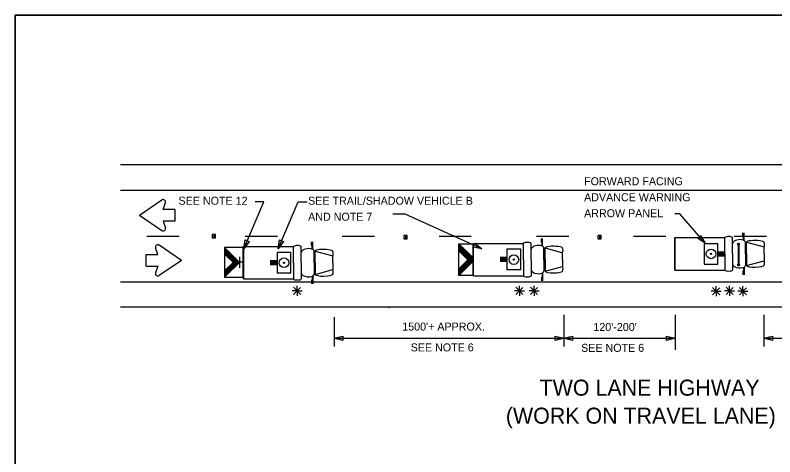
# Model space of a CAD drawing. Extents: x 1374027 to 1374537, y 380415 to 381405.
# Drawn here: x 1374027.1 to 1374084, y 381372.1 to 381405.2 of the extents above; entities that cross this region are included whole.
import ezdxf

# ---------------------------------------------------------------- set-up
doc = ezdxf.new("R2010")
doc.units = 0
for name, color, linetype in [('DSN_DRFT_Junk-No-Plot', 7, 'Continuous'), ('Level 1', 7, 'Continuous'), ('Working Level 1', 7, 'Continuous')]:
    doc.layers.add(name, color=color, linetype=linetype)

msp = doc.modelspace()

# ---------------------------------------------------------------- linework, layer by layer
at = {"layer": 'DSN_DRFT_Junk-No-Plot'}
for points in [[(1374027.083, 381405.174), (1374197.083, 381405.174), (1374197.083, 381295.174), (1374027.083, 381295.174)], [(1374027.083, 381405.174), (1374027.083, 381295.174), (1374197.083, 381295.174), (1374197.083, 381405.174)]]:
    msp.add_lwpolyline(points, close=True, dxfattribs=at)
at = {"layer": 'Level 1'}
for points in [[(1374044.225, 381387.656), (1374045.73, 381391.182), (1374045.061, 381391.182)], [(1374046.798, 381387.656), (1374048.302, 381391.182), (1374048.971, 381391.182)], [(1374062.052, 381387.656), (1374056.327, 381390.262), (1374055.393, 381390.262)]]:
    msp.add_lwpolyline(points, dxfattribs=at)
at = {"layer": 'Working Level 1'}
for p, q in [((1374034.976, 381393.968), (1374114.952, 381393.968)), ((1374034.976, 381392.056), (1374114.952, 381392.056)), ((1374036.403, 381390.173), (1374038.07, 381391.316)), ((1374038.175, 381390.609), (1374038.338, 381391.117)), ((1374039.043, 381390.609), (1374038.175, 381390.609)), ((1374039.043, 381390.609), (1374039.043, 381389.736)), ((1374036.403, 381390.173), (1374038.07, 381389.029)), ((1374039.043, 381389.736), (1374038.175, 381389.736)), ((1374038.175, 381389.736), (1374038.338, 381389.229)), ((1374041.846, 381388.717), (1374041.845, 381388.474)), ((1374042.088, 381388.717), (1374041.846, 381388.717)), ((1374041.968, 381388.717), (1374041.967, 381388.474)), ((1374042.088, 381388.474), (1374042.088, 381388.717)), ((1374056.214, 381388.642), (1374056.213, 381388.399)), ((1374056.456, 381388.642), (1374056.214, 381388.642)), ((1374056.335, 381388.642), (1374056.335, 381388.399)), ((1374056.456, 381388.399), (1374056.456, 381388.642)), ((1374070.758, 381388.656), (1374070.757, 381388.413)), ((1374071, 381388.656), (1374070.758, 381388.656)), ((1374070.879, 381388.656), (1374070.879, 381388.413)), ((1374071, 381388.413), (1374071, 381388.656)), ((1374081.635, 381388.562), (1374081.635, 381388.858)), ((1374081.682, 381388.276), (1374081.682, 381388.858)), ((1374081.722, 381388.276), (1374081.722, 381388.858)), ((1374041.845, 381388.474), (1374042.088, 381388.474)), ((1374049.302, 381387.891), (1374049.302, 381388.188)), ((1374049.349, 381387.605), (1374049.349, 381388.188)), ((1374049.389, 381387.605), (1374049.389, 381388.188)), ((1374056.213, 381388.399), (1374056.456, 381388.399)), ((1374061.427, 381388.059), (1374065.181, 381388.059)), ((1374061.427, 381385.634), (1374061.427, 381388.059)), ((1374065.181, 381386.847), (1374065.181, 381388.059)), ((1374065.757, 381386.847), (1374065.757, 381388.059)), ((1374066.532, 381388.132), (1374066.532, 381388.429)), ((1374066.579, 381387.846), (1374066.579, 381388.429)), ((1374066.619, 381387.846), (1374066.619, 381388.429)), ((1374070.757, 381388.413), (1374071, 381388.413)), ((1374076.53, 381388.489), (1374080.284, 381388.489)), ((1374076.53, 381386.063), (1374076.53, 381388.489)), ((1374076.53, 381388.489), (1374076.53, 381386.064)), ((1374078.735, 381388.053), (1374079.761, 381388.053)), ((1374078.735, 381388.053), (1374078.735, 381386.5)), ((1374079.761, 381386.5), (1374079.761, 381388.053)), ((1374080.284, 381387.276), (1374080.284, 381388.489)), ((1374080.86, 381387.276), (1374080.86, 381388.489)), ((1374081.314, 381388.064), (1374081.314, 381388.064)), ((1374081.823, 381387.276), (1374081.823, 381388.15)), ((1374081.903, 381388.15), (1374083.216, 381387.791)), ((1374081.903, 381387.276), (1374081.903, 381388.15)), ((1374037.771, 381387.224), (1374037.608, 381387.731)), ((1374039.543, 381386.787), (1374037.876, 381387.931)), ((1374042.77, 381387.754), (1374043.889, 381386.637)), ((1374044.197, 381387.819), (1374044.197, 381385.393)), ((1374044.197, 381387.818), (1374047.951, 381387.818)), ((1374044.197, 381385.393), (1374044.197, 381387.818)), ((1374047.951, 381386.606), (1374047.951, 381387.818)), ((1374048.526, 381386.606), (1374048.526, 381387.818)), ((1374049.49, 381386.606), (1374049.49, 381387.479)), ((1374049.57, 381387.479), (1374050.883, 381387.12)), ((1374049.57, 381386.606), (1374049.57, 381387.479)), ((1374060.34, 381388.031), (1374061.376, 381386.996)), ((1374060.34, 381387.513), (1374061.023, 381386.833)), ((1374064.975, 381387.623), (1374063.948, 381387.623)), ((1374063.948, 381387.623), (1374063.948, 381386.07)), ((1374064.975, 381386.07), (1374064.975, 381387.623)), ((1374066.72, 381386.847), (1374066.72, 381387.72)), ((1374066.8, 381387.72), (1374068.113, 381387.361)), ((1374066.8, 381386.847), (1374066.8, 381387.72)), ((1374081.226, 381388.014), (1374081.226, 381388.014)), ((1374081.288, 381387.979), (1374081.288, 381386.473)), ((1374081.292, 381387.979), (1374081.292, 381386.473)), ((1374081.297, 381387.979), (1374081.297, 381386.473)), ((1374081.305, 381387.979), (1374081.305, 381386.473)), ((1374081.316, 381387.979), (1374081.316, 381386.473)), ((1374083.216, 381387.276), (1374083.216, 381387.791)), ((1374036.904, 381386.351), (1374036.904, 381387.224)), ((1374036.904, 381387.224), (1374037.771, 381387.224)), ((1374042.77, 381387.269), (1374043.411, 381386.63)), ((1374043.926, 381386.217), (1374043.926, 381387.058)), ((1374047.744, 381387.382), (1374046.718, 381387.382)), ((1374046.718, 381387.382), (1374046.718, 381385.829)), ((1374047.744, 381385.829), (1374047.744, 381387.382)), ((1374050.883, 381386.606), (1374050.883, 381387.12)), ((1374063.948, 381387.002), (1374063.426, 381387.002)), ((1374063.948, 381386.924), (1374063.426, 381386.924)), ((1374068.113, 381386.847), (1374068.113, 381387.361)), ((1374079.761, 381387.432), (1374080.284, 381387.432)), ((1374079.761, 381387.354), (1374080.284, 381387.354)), ((1374079.761, 381387.276), (1374080.284, 381387.276)), ((1374079.761, 381387.199), (1374080.284, 381387.199)), ((1374079.761, 381387.121), (1374080.284, 381387.121)), ((1374080.284, 381387.276), (1374080.284, 381386.064)), ((1374080.86, 381387.276), (1374080.86, 381386.064)), ((1374081.823, 381387.276), (1374081.823, 381386.403)), ((1374081.903, 381387.276), (1374081.903, 381386.403)), ((1374083.216, 381387.276), (1374083.216, 381386.762)), ((1374036.904, 381386.351), (1374037.771, 381386.351)), ((1374037.771, 381386.351), (1374037.608, 381385.844)), ((1374039.543, 381386.787), (1374037.876, 381385.644)), ((1374042.77, 381385.991), (1374043.411, 381386.63)), ((1374042.777, 381385.524), (1374043.889, 381386.637)), ((1374044.16, 381386.657), (1374043.919, 381386.657)), ((1374046.718, 381386.761), (1374046.195, 381386.761)), ((1374046.718, 381386.683), (1374046.195, 381386.683)), ((1374046.718, 381386.606), (1374046.195, 381386.606)), ((1374046.718, 381386.528), (1374046.195, 381386.528)), ((1374046.718, 381386.45), (1374046.195, 381386.45)), ((1374047.951, 381386.606), (1374047.951, 381385.393)), ((1374048.526, 381386.606), (1374048.526, 381385.393)), ((1374049.49, 381386.606), (1374049.49, 381385.732)), ((1374049.57, 381386.606), (1374049.57, 381385.732)), ((1374050.883, 381386.606), (1374050.883, 381386.091)), ((1374060.34, 381386.151), (1374061.023, 381386.833)), ((1374060.346, 381385.653), (1374061.371, 381386.678)), ((1374063.948, 381386.847), (1374063.426, 381386.847)), ((1374063.948, 381386.769), (1374063.426, 381386.769)), ((1374063.948, 381386.691), (1374063.426, 381386.691)), ((1374065.181, 381386.847), (1374065.181, 381385.634)), ((1374065.757, 381386.847), (1374065.757, 381385.634)), ((1374066.72, 381386.847), (1374066.72, 381385.973)), ((1374066.8, 381386.847), (1374066.8, 381385.973)), ((1374068.113, 381386.847), (1374068.113, 381386.332)), ((1374078.735, 381386.5), (1374079.761, 381386.5)), ((1374081.231, 381386.46), (1374081.231, 381386.46)), ((1374081.318, 381386.511), (1374081.318, 381386.511)), ((1374081.903, 381386.403), (1374083.216, 381386.762)), ((1374047.744, 381385.829), (1374046.718, 381385.829)), ((1374049.57, 381385.732), (1374050.883, 381386.091)), ((1374064.975, 381386.07), (1374063.948, 381386.07)), ((1374066.579, 381385.847), (1374066.579, 381385.264)), ((1374066.619, 381385.847), (1374066.619, 381385.264)), ((1374066.8, 381385.973), (1374068.113, 381386.332)), ((1374076.53, 381386.064), (1374080.284, 381386.064)), ((1374081.635, 381385.991), (1374081.635, 381385.694)), ((1374081.682, 381386.277), (1374081.682, 381385.694)), ((1374081.722, 381386.277), (1374081.722, 381385.694)), ((1374044.197, 381385.393), (1374047.951, 381385.393)), ((1374049.302, 381385.32), (1374049.302, 381385.023)), ((1374049.349, 381385.606), (1374049.349, 381385.023)), ((1374049.389, 381385.606), (1374049.389, 381385.023)), ((1374061.427, 381385.634), (1374065.181, 381385.634)), ((1374066.532, 381385.561), (1374066.532, 381385.264)), ((1374034.976, 381385.186), (1374114.952, 381385.186)), ((1374048.222, 381384.499), (1374047.956, 381384.765)), ((1374048.215, 381384.494), (1374048.482, 381384.76)), ((1374048.222, 381384.499), (1374048.222, 381384.875)), ((1374064.881, 381384.499), (1374064.615, 381384.765)), ((1374064.875, 381384.494), (1374065.141, 381384.76)), ((1374064.881, 381384.499), (1374064.881, 381384.875)), ((1374065.979, 381384.499), (1374065.713, 381384.765)), ((1374065.973, 381384.494), (1374066.239, 381384.76)), ((1374065.979, 381384.499), (1374065.979, 381384.875)), ((1374079.631, 381384.475), (1374079.365, 381384.741)), ((1374079.625, 381384.47), (1374079.891, 381384.736)), ((1374079.631, 381384.475), (1374079.631, 381384.852)), ((1374080.634, 381384.499), (1374080.368, 381384.765)), ((1374080.627, 381384.494), (1374080.894, 381384.76)), ((1374080.634, 381384.499), (1374080.634, 381384.875)), ((1374081.636, 381384.475), (1374081.37, 381384.741)), ((1374081.63, 381384.47), (1374081.896, 381384.736)), ((1374081.636, 381384.475), (1374081.636, 381384.852)), ((1374048.222, 381384.499), (1374047.845, 381384.499)), ((1374048.222, 381384.499), (1374047.956, 381384.233)), ((1374048.222, 381384.499), (1374048.488, 381384.233)), ((1374048.222, 381384.499), (1374048.222, 381384.123)), ((1374048.222, 381384.499), (1374048.598, 381384.499)), ((1374064.881, 381384.499), (1374064.505, 381384.499)), ((1374064.881, 381384.499), (1374064.615, 381384.233)), ((1374064.881, 381384.499), (1374065.147, 381384.233)), ((1374064.881, 381384.499), (1374064.881, 381384.123)), ((1374064.881, 381384.499), (1374065.257, 381384.499)), ((1374065.979, 381384.499), (1374065.603, 381384.499)), ((1374065.979, 381384.499), (1374065.713, 381384.233)), ((1374065.979, 381384.499), (1374066.245, 381384.233)), ((1374065.979, 381384.499), (1374065.979, 381384.123)), ((1374065.979, 381384.499), (1374066.355, 381384.499)), ((1374079.631, 381384.475), (1374079.255, 381384.475)), ((1374079.631, 381384.475), (1374079.365, 381384.209)), ((1374079.631, 381384.475), (1374079.897, 381384.209)), ((1374079.631, 381384.475), (1374079.631, 381384.099)), ((1374079.631, 381384.475), (1374080.007, 381384.475)), ((1374080.634, 381384.499), (1374080.257, 381384.499)), ((1374080.634, 381384.499), (1374080.368, 381384.233)), ((1374080.634, 381384.499), (1374080.9, 381384.233)), ((1374080.634, 381384.499), (1374080.634, 381384.123)), ((1374080.634, 381384.499), (1374081.01, 381384.499)), ((1374081.636, 381384.475), (1374081.26, 381384.475)), ((1374081.636, 381384.475), (1374081.37, 381384.209)), ((1374081.636, 381384.475), (1374081.902, 381384.209)), ((1374081.636, 381384.475), (1374081.636, 381384.099)), ((1374081.636, 381384.475), (1374082.012, 381384.475)), ((1374034.976, 381383.298), (1374114.952, 381383.298)), ((1374055.124, 381383.238), (1374055.076, 381383.238)), ((1374050.99, 381382.519), (1374050.99, 381380.339)), ((1374068.217, 381382.692), (1374068.217, 381380.339)), ((1374076.546, 381382.692), (1374076.546, 381380.075)), ((1374083.205, 381382.692), (1374083.205, 381380.339)), ((1374050.99, 381380.946), (1374068.217, 381380.946)), ((1374050.99, 381380.946), (1374051.567, 381380.946)), ((1374068.217, 381380.946), (1374068.101, 381380.946)), ((1374068.217, 381380.946), (1374068.671, 381380.946)), ((1374068.217, 381380.946), (1374076.546, 381380.946)), ((1374076.546, 381380.946), (1374076.094, 381380.946)), ((1374083.205, 381380.946), (1374083.659, 381380.946)), ((1374083.214, 381380.946), (1374091.543, 381380.946))]:
    msp.add_line(p, q, dxfattribs=at)
for points in [[(1374078.815, 381388.066), (1374076.906, 381390.284), (1374076.542, 381390.284)], [(1374036.961, 381388.61), (1374039.387, 381388.61)], [(1374044.325, 381388.61), (1374046.751, 381388.61)], [(1374051.601, 381388.61), (1374054.026, 381388.61)], [(1374058.876, 381388.61), (1374061.272, 381388.61)], [(1374066.152, 381388.61), (1374068.577, 381388.61)], [(1374073.427, 381388.61), (1374075.853, 381388.61)], [(1374080.977, 381388.61), (1374083.402, 381388.61)], [(1374081.241, 381388.045), (1374081.31, 381387.927)], [(1374081.252, 381388.055), (1374081.324, 381387.931)], [(1374081.264, 381388.064), (1374081.337, 381387.938)], [(1374081.279, 381388.068), (1374081.348, 381387.948)], [(1374081.294, 381388.071), (1374081.358, 381387.96)], [(1374081.312, 381388.069), (1374081.365, 381387.977)], [(1374081.333, 381388.061), (1374081.369, 381388)], [(1374042.77, 381387.702), (1374043.361, 381386.68)], [(1374042.77, 381387.614), (1374043.244, 381386.794)], [(1374042.77, 381387.526), (1374043.127, 381386.909)], [(1374042.82, 381387.705), (1374043.601, 381386.351)], [(1374042.94, 381387.585), (1374043.634, 381386.383)], [(1374060.34, 381387.976), (1374060.969, 381386.886)], [(1374060.34, 381387.882), (1374060.845, 381387.007)], [(1374060.34, 381387.788), (1374060.72, 381387.129)], [(1374060.34, 381387.694), (1374060.596, 381387.252)], [(1374060.34, 381387.6), (1374060.471, 381387.374)], [(1374060.34, 381387.507), (1374060.346, 381387.496)], [(1374060.393, 381387.979), (1374061.226, 381386.535)], [(1374060.521, 381387.85), (1374061.261, 381386.569)], [(1374060.649, 381387.723), (1374061.295, 381386.603)], [(1374060.777, 381387.595), (1374061.329, 381386.637)], [(1374081.224, 381387.987), (1374081.251, 381387.942)], [(1374081.226, 381388.014), (1374081.275, 381387.929)], [(1374081.232, 381388.032), (1374081.294, 381387.925)], [(1374042.77, 381387.438), (1374043.01, 381387.024)], [(1374042.77, 381387.35), (1374042.893, 381387.138)], [(1374042.77, 381387.262), (1374042.777, 381387.253)], [(1374043.059, 381387.465), (1374043.666, 381386.415)], [(1374043.18, 381387.345), (1374043.698, 381386.447)], [(1374043.299, 381387.225), (1374043.73, 381386.479)], [(1374043.419, 381387.105), (1374043.764, 381386.51)], [(1374043.539, 381386.986), (1374043.797, 381386.54)], [(1374060.904, 381387.467), (1374061.364, 381386.671)], [(1374061.032, 381387.339), (1374061.372, 381386.751)], [(1374061.16, 381387.212), (1374061.374, 381386.843)], [(1374061.288, 381387.085), (1374061.375, 381386.933)], [(1374043.139, 381386.36), (1374043.311, 381386.062)], [(1374043.172, 381386.392), (1374043.344, 381386.094)], [(1374043.204, 381386.424), (1374043.376, 381386.127)], [(1374043.236, 381386.456), (1374043.408, 381386.158)], [(1374043.268, 381386.489), (1374043.441, 381386.19)], [(1374043.3, 381386.521), (1374043.473, 381386.223)], [(1374043.333, 381386.552), (1374043.505, 381386.254)], [(1374043.364, 381386.585), (1374043.538, 381386.287)], [(1374043.397, 381386.617), (1374043.57, 381386.319)], [(1374043.659, 381386.867), (1374043.826, 381386.577)], [(1374043.77, 381386.758), (1374043.856, 381386.608)], [(1374060.528, 381386.338), (1374060.711, 381386.021)], [(1374060.562, 381386.372), (1374060.745, 381386.056)], [(1374060.597, 381386.407), (1374060.779, 381386.09)], [(1374060.631, 381386.441), (1374060.814, 381386.124)], [(1374060.665, 381386.476), (1374060.848, 381386.158)], [(1374060.699, 381386.51), (1374060.883, 381386.192)], [(1374060.733, 381386.544), (1374060.917, 381386.227)], [(1374060.768, 381386.578), (1374060.952, 381386.261)], [(1374060.802, 381386.613), (1374060.986, 381386.295)], [(1374060.837, 381386.647), (1374061.02, 381386.329)], [(1374060.871, 381386.681), (1374061.054, 381386.363)], [(1374060.905, 381386.716), (1374061.089, 381386.398)], [(1374060.94, 381386.75), (1374061.123, 381386.432)], [(1374060.974, 381386.784), (1374061.158, 381386.466)], [(1374061.008, 381386.818), (1374061.192, 381386.5)], [(1374081.229, 381386.434), (1374081.255, 381386.388)], [(1374081.231, 381386.46), (1374081.279, 381386.376)], [(1374081.237, 381386.479), (1374081.298, 381386.372)], [(1374081.246, 381386.492), (1374081.314, 381386.374)], [(1374081.256, 381386.502), (1374081.328, 381386.378)], [(1374081.268, 381386.51), (1374081.341, 381386.385)], [(1374081.283, 381386.514), (1374081.352, 381386.394)], [(1374081.298, 381386.518), (1374081.362, 381386.407)], [(1374081.316, 381386.516), (1374081.369, 381386.423)], [(1374081.338, 381386.508), (1374081.373, 381386.446)], [(1374042.77, 381385.944), (1374042.925, 381385.677)], [(1374042.77, 381385.856), (1374042.892, 381385.645)], [(1374042.77, 381385.768), (1374042.86, 381385.613)], [(1374042.785, 381386.006), (1374042.957, 381385.71)], [(1374042.818, 381386.039), (1374042.989, 381385.741)], [(1374042.85, 381386.07), (1374043.021, 381385.774)], [(1374042.882, 381386.103), (1374043.054, 381385.805)], [(1374042.914, 381386.135), (1374043.086, 381385.838)], [(1374042.946, 381386.167), (1374043.118, 381385.87)], [(1374042.978, 381386.199), (1374043.15, 381385.902)], [(1374043.011, 381386.231), (1374043.183, 381385.934)], [(1374043.043, 381386.263), (1374043.215, 381385.966)], [(1374043.075, 381386.296), (1374043.247, 381385.998)], [(1374043.107, 381386.328), (1374043.279, 381386.03)], [(1374060.34, 381386.101), (1374060.505, 381385.816)], [(1374060.34, 381386.007), (1374060.47, 381385.782)], [(1374060.34, 381385.912), (1374060.436, 381385.748)], [(1374060.34, 381385.819), (1374060.401, 381385.713)], [(1374060.356, 381386.167), (1374060.538, 381385.851)], [(1374060.391, 381386.201), (1374060.573, 381385.884)], [(1374060.424, 381386.235), (1374060.607, 381385.919)], [(1374060.459, 381386.27), (1374060.642, 381385.953)], [(1374060.493, 381386.304), (1374060.676, 381385.988)], [(1374042.77, 381385.68), (1374042.828, 381385.581)], [(1374042.77, 381385.592), (1374042.795, 381385.55)], [(1374060.34, 381385.725), (1374060.367, 381385.68)]]:
    msp.add_lwpolyline(points, dxfattribs=at)
for points in [[(1374078.477, 381388.645), (1374078.815, 381388.066), (1374078.245, 381388.418)], [(1374044.63, 381388.19), (1374044.225, 381387.656), (1374044.331, 381388.317)], [(1374047.202, 381388.19), (1374046.798, 381387.656), (1374046.903, 381388.317)], [(1374061.528, 381388.073), (1374062.052, 381387.656), (1374061.394, 381387.777)], [(1374042.77, 381387.754), (1374042.77, 381385.524), (1374044.164, 381385.524), (1374044.164, 381387.754)], [(1374061.379, 381385.653), (1374060.34, 381385.653), (1374060.34, 381388.031), (1374061.379, 381388.031)], [(1374051.64, 381380.783), (1374050.99, 381380.946), (1374051.64, 381381.108)], [(1374067.567, 381381.108), (1374068.217, 381380.946), (1374067.567, 381380.783)], [(1374068.867, 381380.783), (1374068.217, 381380.946), (1374068.867, 381381.108)], [(1374075.896, 381381.108), (1374076.546, 381380.946), (1374075.896, 381380.783)], [(1374083.855, 381380.783), (1374083.205, 381380.946), (1374083.855, 381381.108)]]:
    msp.add_lwpolyline(points, close=True, dxfattribs=at)
for centre, radius in [((1374081.296, 381387.998), 0.0728), ((1374079.248, 381387.276), 0.362), ((1374047.231, 381386.606), 0.362), ((1374064.462, 381386.846), 0.362), ((1374079.248, 381387.276), 0.0451), ((1374047.231, 381386.606), 0.0451), ((1374064.462, 381386.846), 0.0451), ((1374081.3, 381386.445), 0.0728)]:
    msp.add_circle(centre, radius, dxfattribs=at)
for centre, radius, start, end in [((1374038.17, 381391.17), 0.177, 342.1824, 124.4455), ((1374038.17, 381389.175), 0.177, 235.5545, 17.8176), ((1374082.895, 381387.963), 0.364, 331.8801, 28.1199), ((1374037.776, 381387.785), 0.177, 55.5545, 197.8176), ((1374067.792, 381387.533), 0.364, 331.8801, 28.1199), ((1374050.561, 381387.292), 0.364, 331.8801, 28.1199), ((1374082.895, 381386.59), 0.364, 331.8801, 28.1199), ((1374037.776, 381385.79), 0.177, 162.1824, 304.4455), ((1374050.561, 381385.919), 0.364, 331.8801, 28.1199), ((1374067.792, 381386.16), 0.364, 331.8801, 28.1199)]:
    msp.add_arc(centre, radius, start, end, dxfattribs=at)
for centre, major_axis, ratio, start_param, end_param in [((1374065.469, 381388.059), (0.288, 0), 0.269913, 0, 3.141593), ((1374080.572, 381388.489), (0.288, 0), 0.269913, 0, 3.141593), ((1374081.341, 381388.09), (0.482, 0.06), 0.503092, 0, 3.141593), ((1374082.56, 381388.142), (0.656, -0.008), 0.2034, 0, 3.141593), ((1374048.239, 381387.818), (0.288, 0), 0.269913, 0, 3.141593), ((1374049.008, 381387.419), (0.482, 0.06), 0.503092, 0, 3.141593), ((1374050.226, 381387.472), (0.656, -0.008), 0.2034, 0, 3.141593), ((1374066.238, 381387.66), (0.482, 0.06), 0.503092, 0, 3.141593), ((1374067.457, 381387.712), (0.656, -0.008), 0.2034, 0, 3.141593), ((1374081.341, 381386.463), (0.482, -0.06), 0.503092, 3.141593, 6.283185), ((1374082.56, 381386.41), (0.656, 0.008), 0.2034, 3.141593, 6.283185), ((1374049.008, 381385.792), (0.482, -0.06), 0.503092, 3.141593, 6.283185), ((1374066.238, 381386.033), (0.482, -0.06), 0.503092, 3.141593, 6.283185), ((1374067.457, 381385.98), (0.656, 0.008), 0.2034, 3.141593, 6.283185), ((1374080.572, 381386.064), (0.288, 0), 0.269913, 3.141593, 6.283185), ((1374048.239, 381385.393), (0.288, 0), 0.269913, 3.141593, 6.283185), ((1374050.226, 381385.74), (0.656, 0.008), 0.2034, 3.141593, 6.283185), ((1374065.469, 381385.634), (0.288, 0), 0.269913, 3.141593, 6.283185)]:
    msp.add_ellipse(centre, major_axis=major_axis, ratio=ratio, start_param=start_param, end_param=end_param, dxfattribs=at)

# ---------------------------------------------------------------- texts
for s, height, p in [('FORWARD FACING', 0.6, (1374069.728, 381392.42)), ('SEE NOTE 12 ', 0.6, (1374039.328, 381390.959)), ('SEE TRAIL/SHADOW VEHICLE B', 0.6, (1374049.041, 381390.959)), ('ADVANCE WARNING ', 0.6, (1374069.728, 381391.22)), ('AND NOTE 7 ', 0.6, (1374049.041, 381389.759)), ('ARROW PANEL', 0.6, (1374069.728, 381390.02)), ("1500'+ APPROX.", 0.6, (1374056.098, 381381.52)), ("120'-200'", 0.6, (1374070.425, 381381.488)), ('SEE NOTE 6', 0.6, (1374056.729, 381379.959)), ('SEE NOTE 6', 0.6, (1374069.506, 381379.926)), ('TWO LANE HIGHWAY', 1.2, (1374066.392, 381376.641)), ('(WORK ON TRAVEL LANE)', 1.2, (1374063.86, 381374.541))]:
    msp.add_text(s, height=height, dxfattribs=at).set_placement(p)

doc.saveas('drawing.dxf')
